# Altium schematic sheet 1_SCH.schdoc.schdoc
size 309 x 223 mm; Symbol: Sheet-Symbol_A4; Device: Sheet-Symbol_A4; Company: Rex.Tang; Version: V1.0; Page Size: A4; @Project Name: PCIe Slot to PI5 Interface; @Page Count: 1; @Update Date: 2024-08-07; @Create Date: 2024-01-23; @Schematic Name: open HAT-PCIe; @Page No: 1; @Page Name: SCH
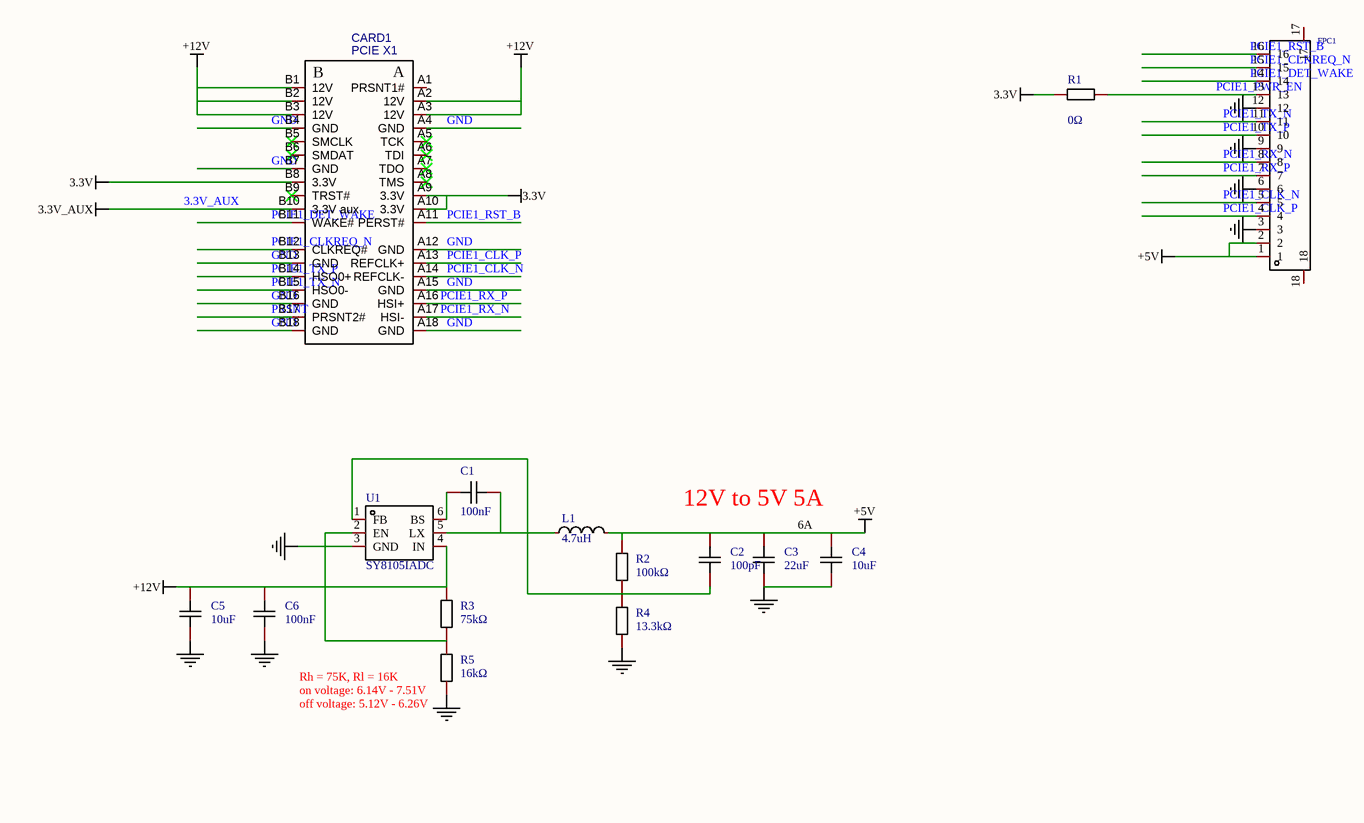
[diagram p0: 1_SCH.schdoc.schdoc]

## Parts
C1  value 100nF  [C0603]  (hidden comment: CC0603KRX7R9BB104)
C2  value 100pF  [C0603]  (hidden comment: CC0603JRNPO9BN101)
C3  value 22uF  [C0603]  (hidden comment: CL10A226MQ8NRNC)
C4  value 10uF  [C0603]  (hidden comment: CL10A106KP8NNNC)
C5  value 10uF  [C0603]  (hidden comment: CL10A106KP8NNNC)
C6  value 100nF  [C0603]  (hidden comment: CC0603KRX7R9BB104)
CARD1  PCIE X1  [PCIE X1金手指]
FPC1  FPC-05F-16PH20  [FPC-SMD_16P-P0.50_FPC-05F-16PH20]  (value not drawn)
L1  4.7uH  [IND-SMD_L7.0-W6.6]
R1  value 0Ω  [R0603]  (hidden comment: 0603WAF0000T5E)
R2  value 100kΩ  [R0603]  (hidden comment: RC0603FR-07100KL)
R3  value 75kΩ  [R0603]  (hidden comment: 0603WAF7502T5E)
R4  value 13.3kΩ  [R0603]  (hidden comment: 0603WAF1332T5E)
R5  value 16kΩ  [R0603]  (hidden comment: 0603WAF1602T5E)
U1  SY8105IADC  [TSOT-23-6_L2.9-W1.6-P0.95-LS2.8-BR]

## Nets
3.3V: CARD1.A9(3.3V) CARD1.A10(3.3V) CARD1.B8(3.3V) R1.1
3.3V_AUX: CARD1.B10(3.3V_aux)
+5V: C2.2 C3.2 C4.2 FPC1.1 FPC1.2 L1.2 R2.2
+12V: C5.2 C6.2 CARD1.A2(12V) CARD1.A3(12V) CARD1.B1(12V) CARD1.B2(12V) CARD1.B3(12V) R3.2 U1.4(IN)
GND: C3.1 C4.1 C5.1 C6.1 CARD1.A4(GND) CARD1.A12(GND) CARD1.A15(GND) CARD1.A18(GND) CARD1.B4(GND) CARD1.B7(GND) CARD1.B13(GND) CARD1.B16(GND) CARD1.B18(GND) FPC1.3 FPC1.6 FPC1.9 FPC1.12 R4.1 R5.1 U1.3(GND)
PCIE1_CLK_N: CARD1.A14(REFCLK-) FPC1.5
PCIE1_CLK_P: CARD1.A13(REFCLK+) FPC1.4
PCIE1_CLKREQ_N: CARD1.B12(CLKREQ#) FPC1.15
PCIE1_DET_WAKE: CARD1.B11(WAKE#) FPC1.14
PCIE1_PWR_EN: FPC1.13 R1.2
PCIE1_RST_B: CARD1.A11(PERST#) FPC1.16
PCIE1_RX_N: CARD1.A17(HSI-) FPC1.8
PCIE1_RX_P: CARD1.A16(HSI+) FPC1.7
PCIE1_TX_N: CARD1.B15(HSO0-) FPC1.11
PCIE1_TX_P: CARD1.B14(HSO0+) FPC1.10
PRSNT: CARD1.B17(PRSNT2#)
NetC1_1: C1.1 L1.1 U1.5(LX)
NetC1_2: C1.2 U1.6(BS)
NetC2_1: C2.1 R2.1 R4.2 U1.1(FB)
NetR3_1: R3.1 R5.2 U1.2(EN)

Not connected (* = marked no-connect by the designer): CARD1 A1(PRSNT1#) A5(TCK)* A6(TDI)* A7(TDO)* A8(TMS)* B5(SMCLK)* B6(SMDAT)* B9(TRST#)*; FPC1 17 18

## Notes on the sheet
- 12V to 5V 5A
- 6A
- (near R5) Rh = 75K, Rl = 16K
  on voltage: 6.14V - 7.51V
  off voltage: 5.12V - 6.26V

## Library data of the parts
C1 C6 = CC0603KRX7R9BB104: Manufacturer: YAGEO(国巨); Add into BOM: yes; Tolerance: ±10%; Voltage Rated: 50V; Temperature Coefficient: X7R; Description: 容值:100nF;精度:±10%;额定电压:50V;材质(温度系数):X7R;
C2 = CC0603JRNPO9BN101: Manufacturer: YAGEO(国巨); Add into BOM: yes; Tolerance: ±5%; Voltage Rated: 50V; Temperature Coefficient: NP0; Description: 容值:100pF;精度:±5%;额定电压:50V;材质(温度系数):NP0;
C3 = CL10A226MQ8NRNC: Manufacturer: SAMSUNG(三星); Add into BOM: yes; Tolerance: ±20%; Voltage Rated: 6.3V; Temperature Coefficient: X5R; Description: 容值:22uF;精度:±20%;额定电压:6.3V;材质(温度系数):X5R;
C4 C5 = CL10A106KP8NNNC: Manufacturer: SAMSUNG(三星); Add into BOM: yes; Tolerance: ±10%; Voltage Rated: 10V; Temperature Coefficient: X5R; Description: 容值:10uF;精度:±10%;额定电压:10V;材质(温度系数):X5R;
CARD1 = PCIE X1金手指: Convert to PCB: yes
FPC1 = FPC-05F-16PH20: Manufacturer: XUNPU(讯普); Add into BOM: yes; Pitch: 0.5mm; Number of Contacts: 16P; Locking Feature: 翻盖式; FFC, FCB Thickness: 0.3mm; Description: 间距:0.5mm;触点数量:16P;锁定特性:翻盖式;安装类型:卧贴;触点类型:下接;工作温度范围:-25℃~+85℃;
L1 = MWSA0603S-4R7MT: Manufacturer: Sunlord(顺络); Add into BOM: yes; Tolerance: ±20%; Rated Current: 6A; Saturation Current (Isat): 9A; DC Resistance (DCR): 33mΩ; Description: 类型:-;电感值:4.7uH;精度:±20%;额定电流:6A;饱和电流(Isat):9A;
R1 = 0603WAF0000T5E: Manufacturer: UNI-ROYAL(厚声); Add into BOM: yes; Tolerance: ±1%; Power(Watts): 100mW; Overload Voltage (Max): 75V; Description: 阻值:0Ω;精度:±1%;功率:100mW;电阻类型:厚膜电阻;
R2 = RC0603FR-07100KL: Manufacturer: YAGEO(国巨); Add into BOM: yes; Tolerance: ±1%; Power(Watts): 100mW; Overload Voltage (Max): 75V; Temperature Coefficient: ±100ppm/℃; Description: 电阻类型:厚膜电阻;阻值:100kΩ;精度:±1%;功率:100mW;最大工作电压:75V;温度系数:±100ppm/℃;
R3 = 0603WAF7502T5E: Manufacturer: UNI-ROYAL(厚声); Add into BOM: yes; Tolerance: ±1%; Power(Watts): 100mW; Overload Voltage (Max): 75V; Temperature Coefficient: ±100ppm/℃; Description: 电阻类型:厚膜电阻;阻值:75kΩ;精度:±1%;功率:100mW;最大工作电压:75V;温度系数:±100ppm/℃;
R4 = 0603WAF1332T5E: Manufacturer: UNI-ROYAL(厚声); Add into BOM: yes; Tolerance: ±1%; Power(Watts): 100mW; Overload Voltage (Max): 75V; Temperature Coefficient: ±100ppm/℃; Description: 电阻类型:厚膜电阻;阻值:13.3kΩ;精度:±1%;功率:100mW;最大工作电压:75V;温度系数:±100ppm/℃;
R5 = 0603WAF1602T5E: Manufacturer: UNI-ROYAL(厚声); Symbol: 16KΩ(1602) ±1%; Add into BOM: yes; Tolerance: ±1%; Power(Watts): 100mW; Overload Voltage (Max): 75V; Temperature Coefficient: ±100ppm/℃; Description: 电阻类型:厚膜电阻;阻值:16kΩ;精度:±1%;功率:100mW;最大工作电压:75V;温度系数:±100ppm/℃;
U1 = SY8105IADC: Manufacturer: silergy(矽力杰); Add into BOM: yes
